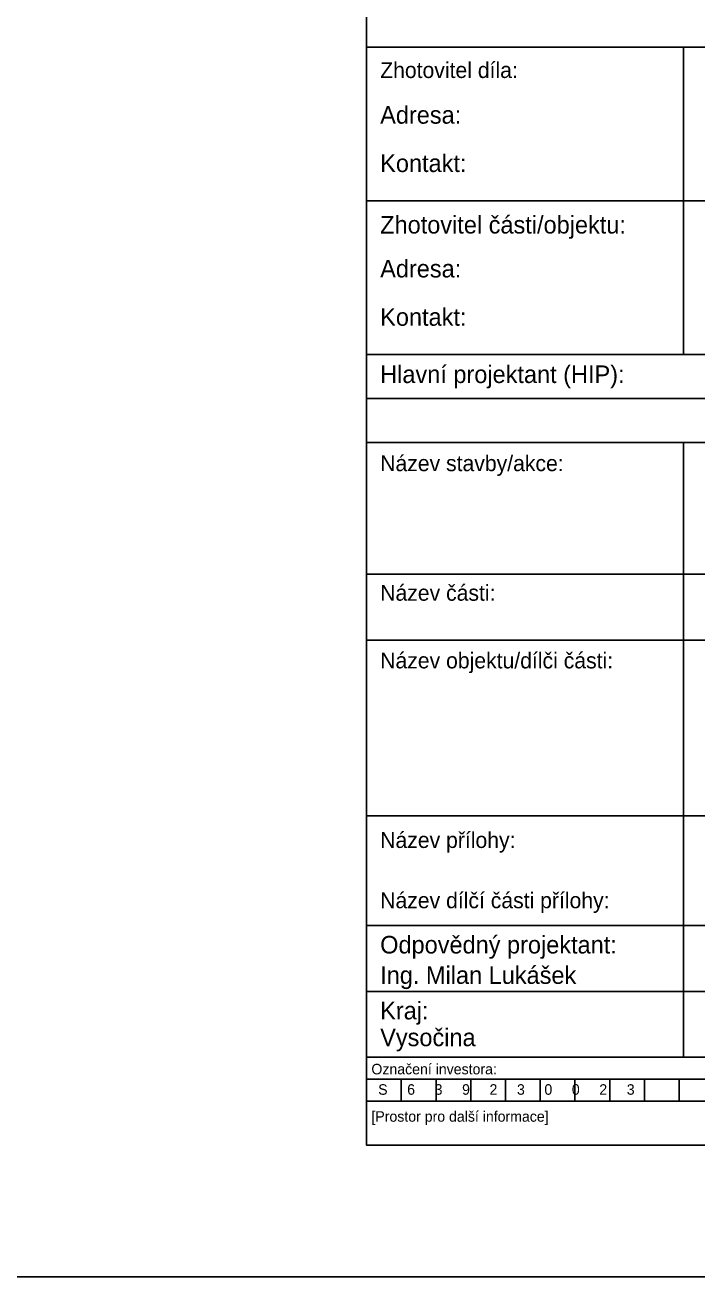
# Model space of a CAD drawing. Extents: x 2343 to 7744, y -5890 to 2050.
# Drawn here: x 6651.2 to 6727.6, y -5890 to -5747.5 of the extents above; entities that cross this region are included whole.
import ezdxf

# ---------------------------------------------------------------- set-up
doc = ezdxf.new("R2010")
doc.units = 0
for name, color, linetype in [('Rozpiska_pole_1', 7, 'Continuous'), ('Rozpiska_pole_6', 7, 'Continuous'), ('Rozpiska_pole_7', 7, 'Continuous'), ('Rozpiska_pole_8', 7, 'Continuous'), ('Vrstva 50', 7, 'Continuous')]:
    doc.layers.add(name, color=color, linetype=linetype)

msp = doc.modelspace()

# ---------------------------------------------------------------- linework, layer by layer
at = {"layer": 'Rozpiska_pole_1'}
msp.add_lwpolyline([(6690, -5610), (6860, -5610), (6860, -5875), (6690, -5875)], close=True, dxfattribs=at)
at = {"layer": 'Rozpiska_pole_6'}
for p, q in [((6726.05, -5785), (6726.05, -5750)), ((6690, -5767.5), (6860, -5767.5)), ((6690, -5785), (6860, -5785))]:
    msp.add_line(p, q, dxfattribs=at)
msp.add_lwpolyline([(6690, -5750), (6860, -5750), (6860, -5790), (6690, -5790)], close=True, dxfattribs=at)
at = {"layer": 'Rozpiska_pole_7'}
for p, q in [((6726.05, -5865), (6726.05, -5795)), ((6690, -5810), (6820.35, -5810)), ((6690, -5817.5), (6820.35, -5817.5)), ((6690, -5837.5), (6820.35, -5837.5)), ((6690, -5850), (6725.55, -5850)), ((6725.55, -5850), (6859.99, -5850)), ((6690, -5857.5), (6859.99, -5857.5))]:
    msp.add_line(p, q, dxfattribs=at)
msp.add_lwpolyline([(6689.99, -5795), (6859.99, -5795), (6859.99, -5865), (6689.99, -5865)], close=True, dxfattribs=at)
at = {"layer": 'Rozpiska_pole_8'}
for p, q in [((6860, -5867.5), (6690, -5867.5)), ((6693.95, -5867.5), (6693.95, -5870)), ((6697.9, -5867.5), (6697.9, -5870)), ((6701.85, -5867.5), (6701.85, -5870)), ((6705.8, -5867.5), (6705.8, -5870)), ((6709.75, -5867.5), (6709.75, -5870)), ((6713.7, -5867.5), (6713.7, -5870)), ((6717.65, -5867.5), (6717.65, -5870)), ((6721.6, -5867.5), (6721.6, -5870)), ((6725.55, -5867.5), (6725.55, -5870))]:
    msp.add_line(p, q, dxfattribs=at)
msp.add_lwpolyline([(6690, -5865), (6860, -5865), (6860, -5870), (6690, -5870)], close=True, dxfattribs=at)
at = {"layer": 'Vrstva 50'}
msp.add_lwpolyline([(5620, -5890), (6880, -5890), (6880, -5593), (5620, -5593)], close=True, dxfattribs=at)

# ---------------------------------------------------------------- texts
at = {"layer": 'Rozpiska_pole_6'}
for s, height, p in [('Zhotovitel díla:', 1.8, (6691.55, -5753.53)), ('Adresa:', 2, (6691.55, -5758.73)), ('Kontakt:', 2, (6691.55, -5764.23)), ('Zhotovitel části/objektu:', 2, (6691.55, -5771.23)), ('Adresa:', 2, (6691.55, -5776.23)), ('Kontakt:', 2, (6691.55, -5781.73)), ('Hlavní projektant (HIP):', 2, (6691.55, -5788.25))]:
    msp.add_text(s, height=height, dxfattribs=at).set_placement(p)
at = {"layer": 'Rozpiska_pole_7'}
for s, height, p in [('Název stavby/akce:', 1.8, (6691.55, -5798.28)), ('Název části:', 1.8, (6691.55, -5813.03)), ('Název objektu/dílči části:', 1.8, (6691.55, -5820.73)), ('Název přílohy:', 1.8, (6691.55, -5841.17)), ('Název dílčí části přílohy:', 1.8, (6691.55, -5848.03)), ('Odpovědný projektant:', 2, (6691.55, -5853.18)), ('Ing. Milan Lukášek', 2, (6691.55, -5856.64)), ('Kraj:', 2, (6691.55, -5860.68)), ('Vysočina', 2, (6691.55, -5863.73))]:
    msp.add_text(s, height=height, dxfattribs=at).set_placement(p)
at = {"layer": 'Rozpiska_pole_8'}
for s, p in [('Označení investora:', (6690.55, -5866.94)), ('S     6     3     9     2     3     0     0     2     3 ', (6691.32, -5869.26)), ('[Prostor pro další informace]', (6690.55, -5872.33))]:
    msp.add_text(s, height=1.2, dxfattribs=at).set_placement(p)

doc.saveas('drawing.dxf')
